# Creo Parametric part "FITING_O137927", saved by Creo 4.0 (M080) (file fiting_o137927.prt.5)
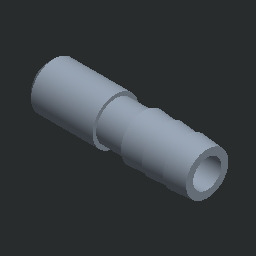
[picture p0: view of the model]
Units: millimeter Kilogram Sec (mmKs); MM, KILOGRAM, SECS
Materials in the file: OCEL

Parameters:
  MFG_WP_MATERIAL = "OCEL"
  NAZOV = "FITING_O137927"
  NORMA = "O 13 7927"
  PTC_MATERIAL_NAME = "OCEL"

Other parameters: HMOTNOST, HUSTOTA, D9, D10, D4, D5, D6, D1, D13, D12

Created from: O137927.PRT

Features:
  1. chamfer

Other named items: BLIND

Named dimensions: svetl

Layers: 1, 2, 3, 4, 5, 6, 7, 8, 9, 10, 11, 12, 13, 14, 15, 16, 17, 18, 19, 20, 21, 22, 23, 24, 25, 26, 27, 28, 29, 30, 31, 32

Family table entries: GENERIC, FITING_G1_4, FITING_O137927, value(d_val), 2/&, 2/ , 2/ , value(i_val), FITING_G3_8, FITING_O137927, 2/I, 2/*, 2/ , 2/$, FITING_G1_2, FITING_O137927, 2/N, 2/0, 2/ , 2/., FITING_G3_4, FITING_O137927, 2/:, 2/3, 2/(, 2/ , 2/4, FITING_G1, FITING_O137927, 2/6, 2/(, 2/ , 2/9, FITING_G11_4, FITING_O137927, 2/T, 2/9, 2/(, 2/ , 2/@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

Surfaces: 8 cylinder, 8 cone, 7 plane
